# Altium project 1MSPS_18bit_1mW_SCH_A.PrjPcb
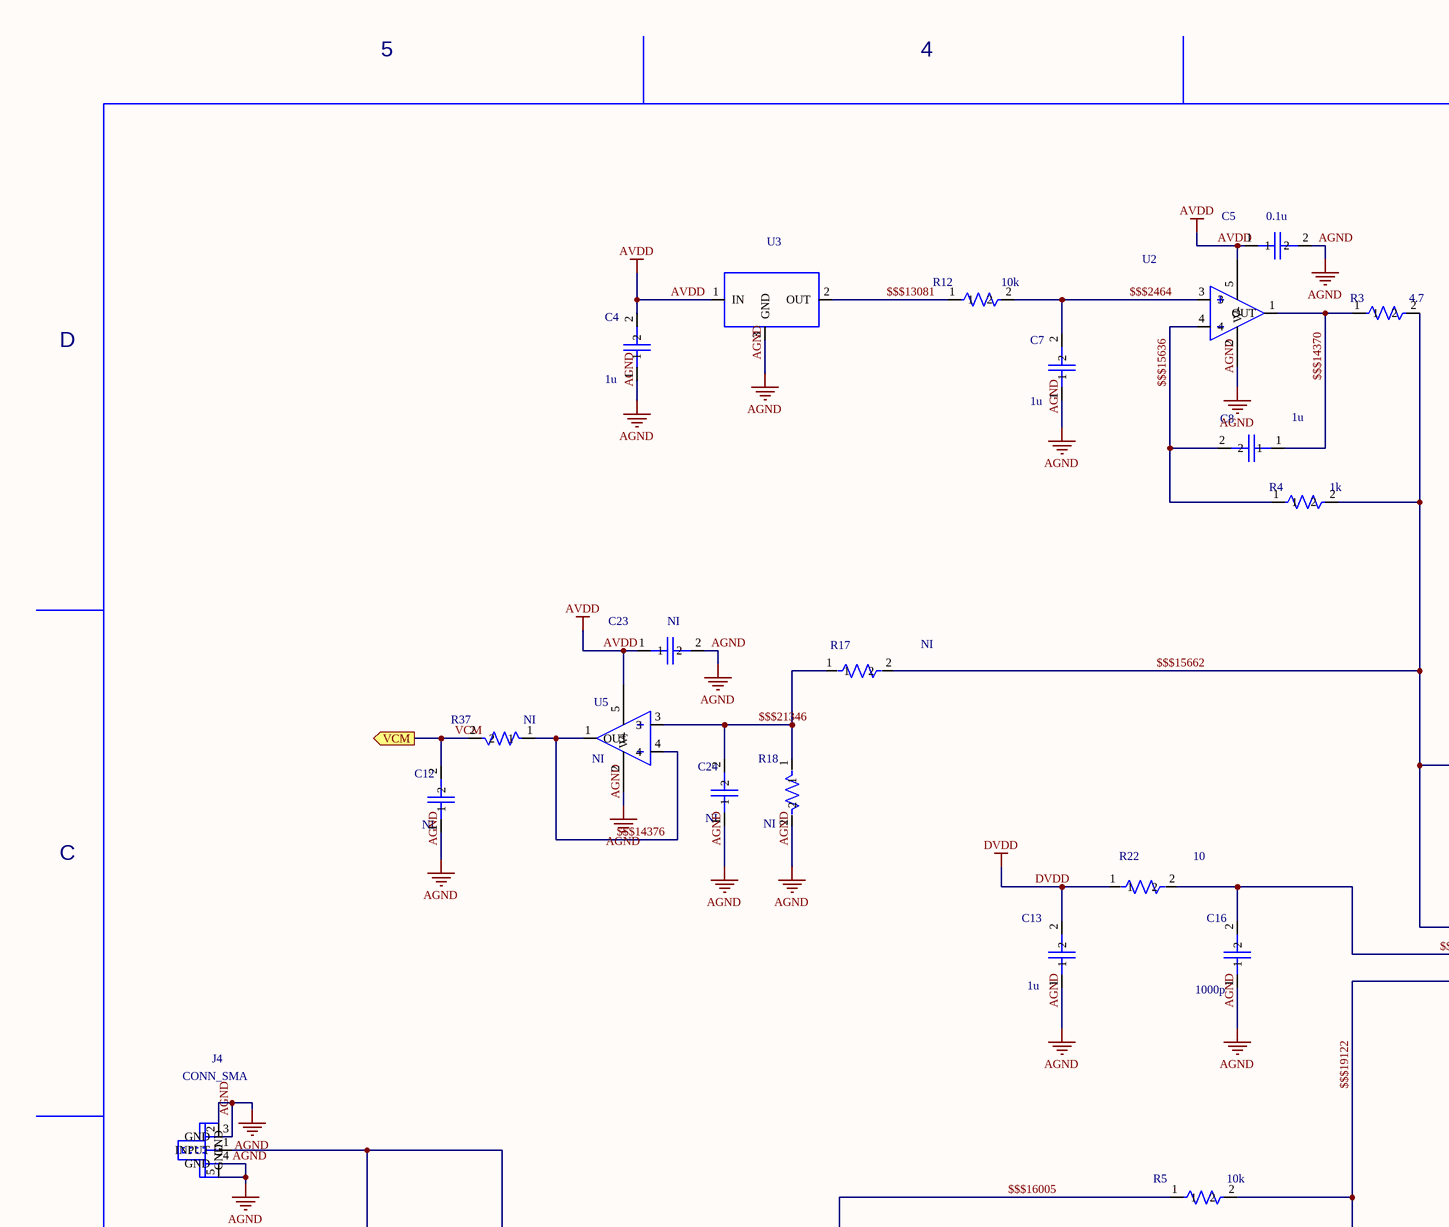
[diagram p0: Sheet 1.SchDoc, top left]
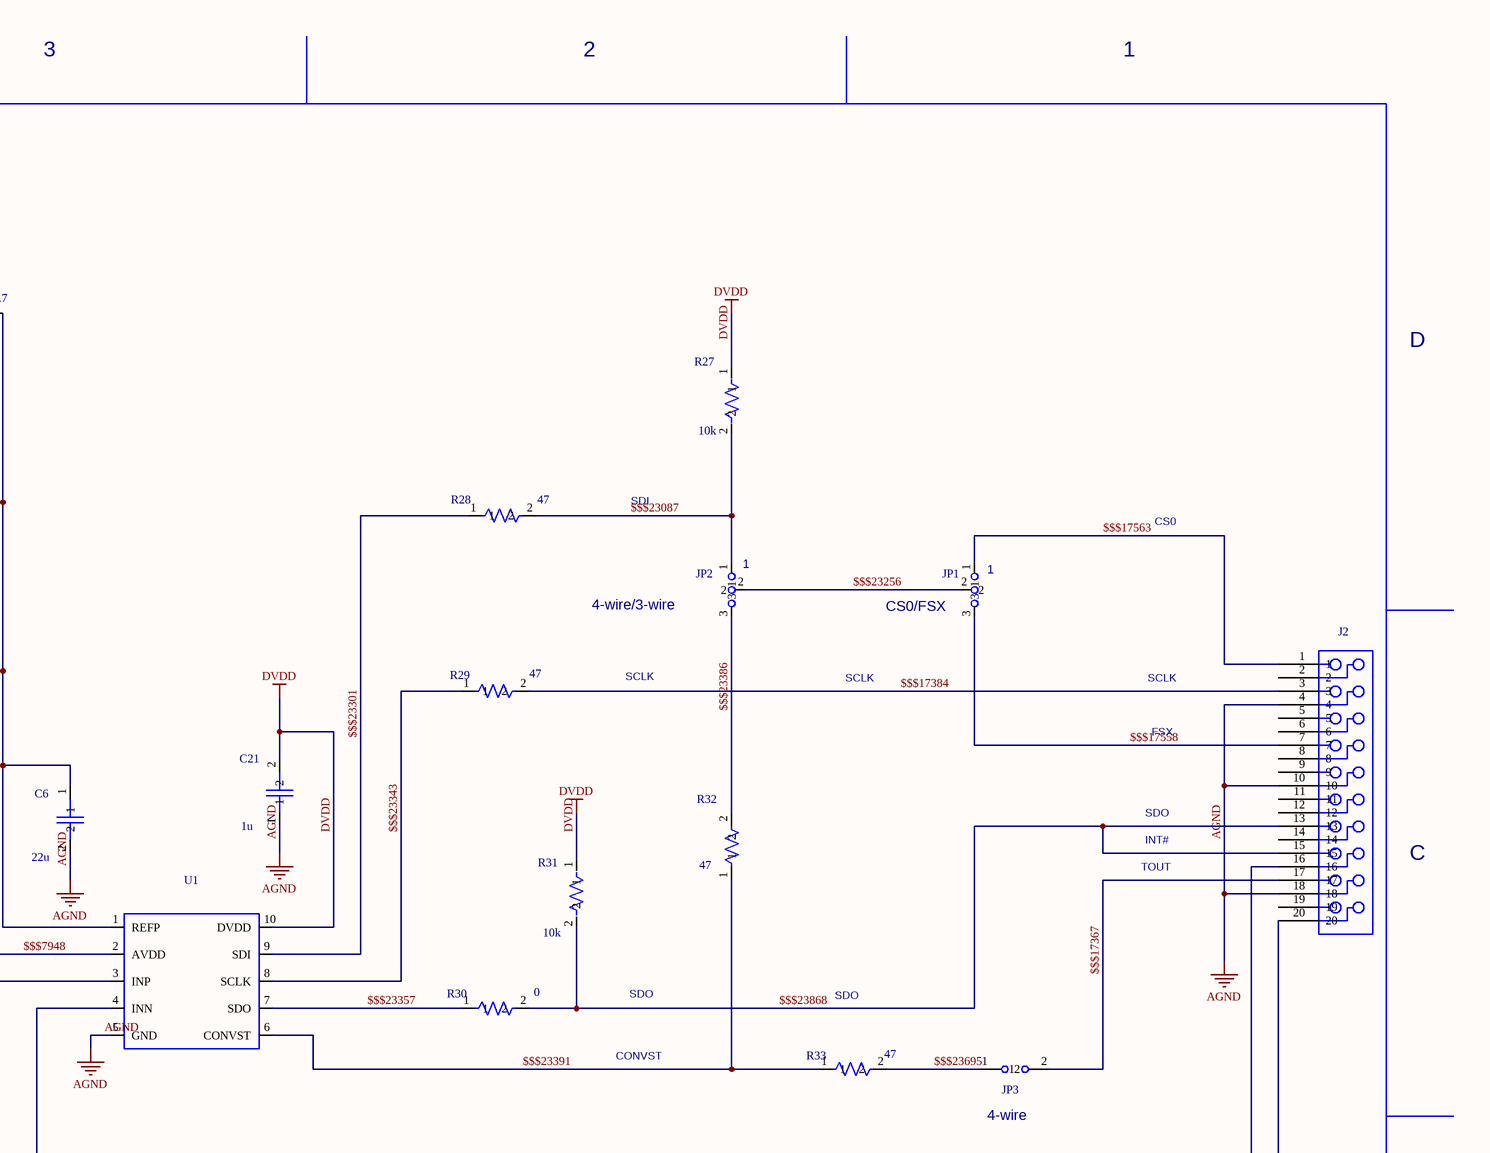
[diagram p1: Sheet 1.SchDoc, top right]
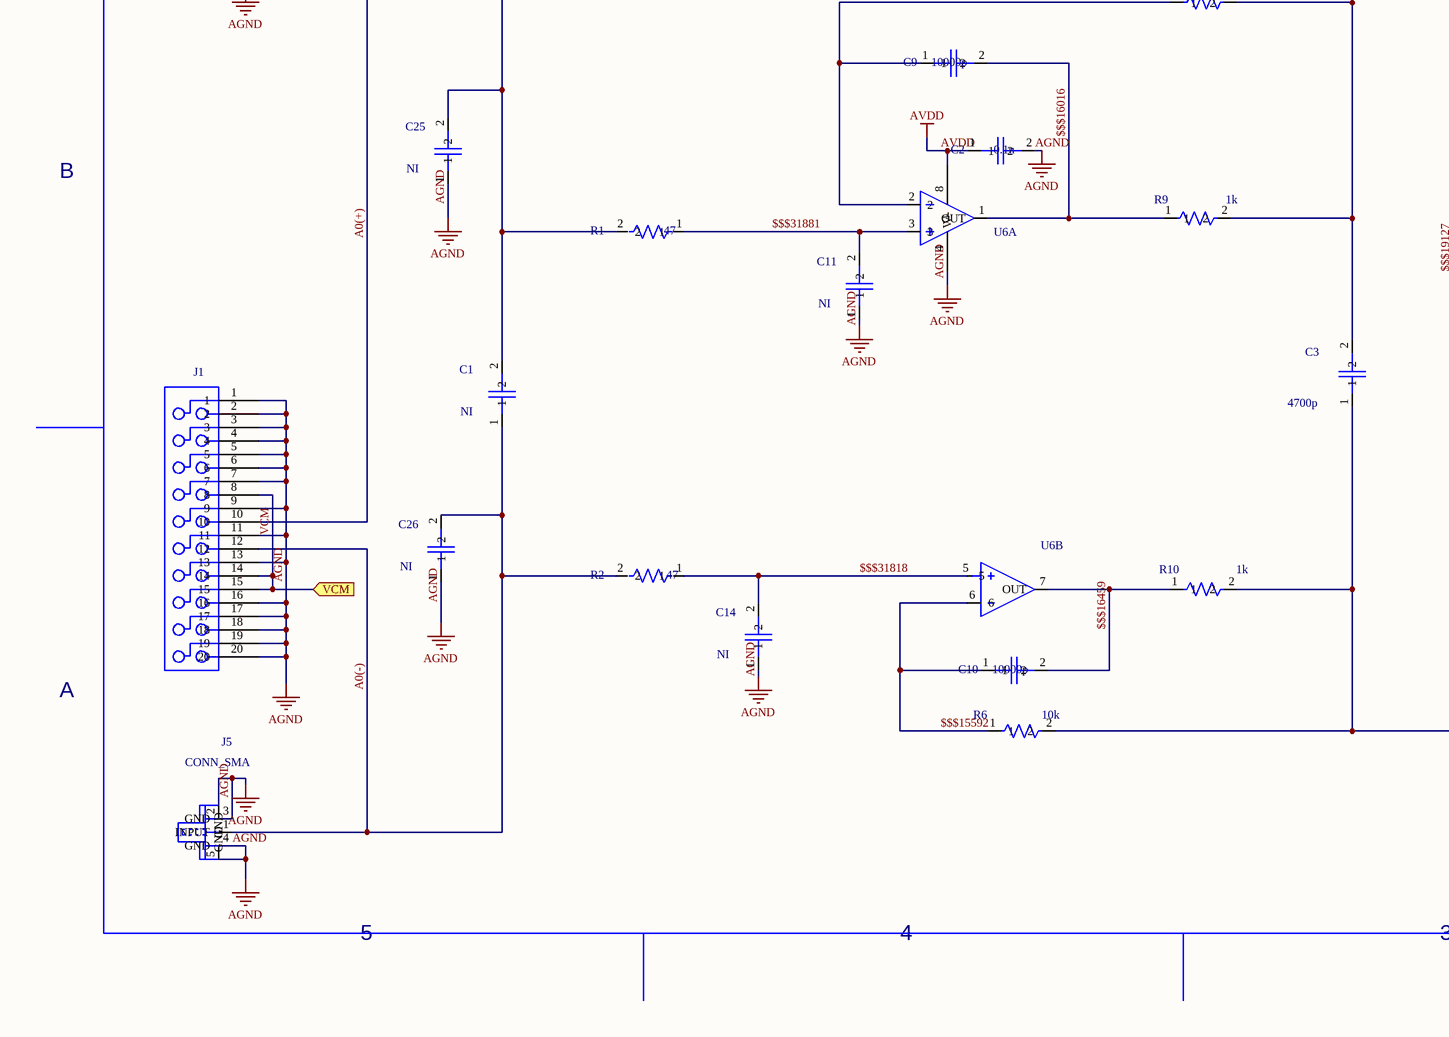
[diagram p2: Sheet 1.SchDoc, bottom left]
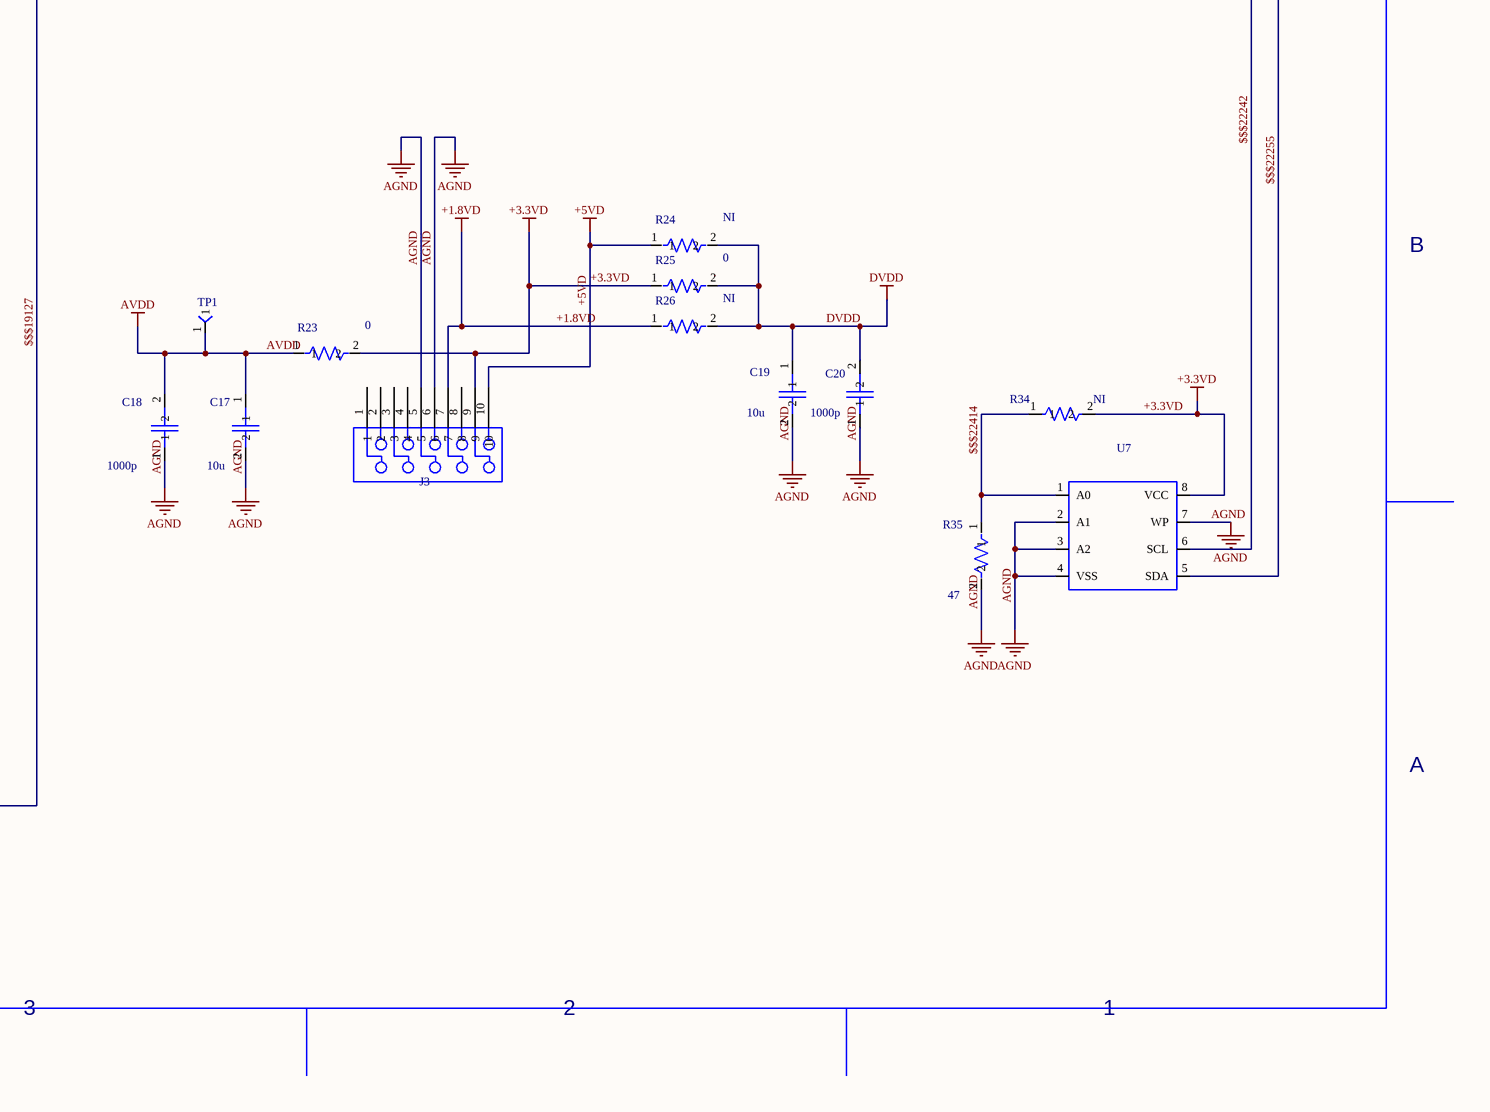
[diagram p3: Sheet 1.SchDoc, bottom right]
1 sheet, 65 parts. Net scope: flat (ports and power ports of the same name join across sheets).

## Sheet Sheet 1.SchDoc: TI Design 18bit 1MSPS 35mW
size 558 x 431 mm; DrawnBy: Rafael Ordonez; Revision: A; Designer: Rafael Ordonez; Edge No.: 6548606

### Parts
C1  value NI  (hidden comment: C0603)
C2  value 0.1u  (hidden comment: C0603)
C3  value 4700p  (hidden comment: C0603)
C4  value 1u  (hidden comment: C0603)
C5  value 0.1u  (hidden comment: C0603)
C6  value 22u  (hidden comment: C1206)
C7  value 1u  (hidden comment: C0603)
C8  value 1u  (hidden comment: C0603)
C9  value 10000p  (hidden comment: C0603)
C10  value 10000p  (hidden comment: C0603)
C11  value NI  (hidden comment: C0603)
C12  value NI  (hidden comment: C0603)
C13  value 1u  (hidden comment: C0603)
C14  value NI  (hidden comment: C0603)
C16  value 1000p  (hidden comment: C0603)
C17  value 10u  (hidden comment: C1206)
C18  value 1000p  (hidden comment: C0603)
C19  value 10u  (hidden comment: C1206)
C20  value 1000p  (hidden comment: C0603)
C21  value 1u  (hidden comment: C0603)
C23  value NI  (hidden comment: C0603)
C24  value NI  (hidden comment: C0603)
C25  value NI  (hidden comment: C0603)
C26  value NI  (hidden comment: C0603)
J1  HEADER_TSM-110-01-T-DV-P_TH  (value not drawn)
J2  HEADER_TSM-110-01-T-DV-P_TH  (value not drawn)
J3  HEADER_TSM-105-01-T-DV-P_TH  (value not drawn)
J4  CONN_SMA
J5  CONN_SMA
JP1  JUMPER_3X100MIL  (value not drawn)
JP2  JUMPER_3X100MIL  (value not drawn)
JP3  JUMPER_2X100MIL  (value not drawn)
R1  value 47  (hidden comment: R0603)
R2  value 47  (hidden comment: R0603)
R3  value 4.7  (hidden comment: R0603)
R4  value 1k  (hidden comment: R0603)
R5  value 10k  (hidden comment: R0603)
R6  value 10k  (hidden comment: R0603)
R9  value 1k  (hidden comment: R0603)
R10  value 1k  (hidden comment: R0603)
R12  value 10k  (hidden comment: R0603)
R17  value NI  (hidden comment: R0603)
R18  value NI  (hidden comment: R0603)
R22  value 10  (hidden comment: R0603)
R23  value 0  (hidden comment: R0603)
R24  value NI  (hidden comment: R0603)
R25  value 0  (hidden comment: R0603)
R26  value NI  (hidden comment: R0603)
R27  value 10k  (hidden comment: R0603)
R28  value 47  (hidden comment: R0603)
R29  value 47  (hidden comment: R0603)
R30  value 0  (hidden comment: R0603)
R31  value 10k  (hidden comment: R0603)
R32  value 47  (hidden comment: R0603)
R33  value 47  (hidden comment: R0603)
R34  value NI  (hidden comment: R0603)
R35  value 47  (hidden comment: R0603)
R37  value NI  (hidden comment: R0603)
TP1  TP-5000-RED  (value not drawn)
U1  ADS886XIDGS  (value not drawn)
U2  OPA313  (value not drawn)
U3  REF33XXAIDBZ  (value not drawn)
U5  value NI  (hidden comment: OPA333)
U6  OPA2320  (value not drawn)  (parts A,B of 2)
U7  24XX256_SERIES  (value not drawn)

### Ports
VCM

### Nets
+1.8VD: J3.7 R26.1
+3.3VD: J3.9 J3.10 R23.2 R24.1 R25.1 R34.2 U7.8(VCC)  [also labelled +5VD]
AGND: C2.2 C4.1 C5.2 C6.2 C7.1 C11.1 C12.1 C12.2 C13.1 C14.1 C16.1 C17.2 C18.1 C19.2 C20.1 C21.1 C23.2 C24.1 C25.1 C26.1 J1.1 J1.2 J1.3 J1.4 J1.5 J1.6 J1.7 J1.8 J1.9 J1.11 J1.13 J1.14 J1.15 J1.16 J1.17 J1.18 J1.19 J1.20 J2.4 J2.10 J2.18 J3.5 J3.6 J4.2(GND) J4.3(GND) J4.4(GND) J4.5(GND) J5.2(GND) J5.3(GND) J5.4(GND) J5.5(GND) R18.2 R35.2 R37.2 U1.5(GND) U2.2(V-) U3.3(GND) U5.2(V-) U6.4(V-) U7.2(A1) U7.3(A2) U7.4(VSS) U7.7(WP) ; port VCM  [also labelled VCM]
AVDD: C2.1 C4.2 C5.1 C17.1 C18.2 C23.1 R23.1 TP1.1 U2.5(V+) U3.1(IN) U5.5(V+) U6.8(V+)
DVDD: C13.2 C19.1 C20.2 C21.2 R22.1 R24.2 R25.2 R26.2 R27.1 R31.1 U1.10(DVDD)
$$$2464: C7.2 R12.2 U2.3
$$$7948: C16.2 R22.2 U1.2(AVDD)
$$$13081: R12.1 U3.2(OUT)
$$$14370: C8.1 R3.1 U2.1(OUT)
$$$14376: R37.1 U5.1(OUT) U5.4
$$$15592: C10.1 R6.1 U6.6
$$$15636: C8.2 R4.1 U2.4
$$$15662: C6.1 R3.2 R4.2 R17.2 U1.1(REFP)
$$$16005: C9.1 R5.1 U6.2
$$$16016: C9.2 R9.1 U6.1(OUT)
$$$16459: C10.2 R10.1 U6.7(OUT)
$$$17367: J2.17 JP3.2
$$$17384: J2.3 R29.2
$$$17558: J2.7 JP1.3
$$$17563: J2.1 JP1.1
$$$19122: C3.2 R5.2 R9.2 U1.3(INP)
$$$19127: C3.1 R6.2 R10.2 U1.4(INN)
$$$21346: C24.2 R17.1 R18.1 U5.3
$$$22242: J2.16 U7.6(SCL)
$$$22255: J2.20 U7.5(SDA)
$$$22414: R34.1 R35.1 U7.1(A0)
$$$23087: JP2.1 R27.2 R28.2
$$$23256: JP1.2 JP2.2
$$$23301: R28.1 U1.9(SDI)
$$$23343: R29.1 U1.8(SCLK)
$$$23357: R30.1 U1.7(SDO)
$$$23386: JP2.3 R32.2
$$$23391: R32.1 R33.1 U1.6(CONVST)
$$$23695: JP3.1 R33.2
$$$23868: J2.13 J2.15 R30.2 R31.2
$$$31818: C14.2 R2.1 U6.5
$$$31881: C11.2 R1.1 U6.3
A0(+): C1.2 C25.2 J1.10 J4.1(INPUT) R1.2
A0(-): C1.1 C26.2 J1.12 J5.1(INPUT) R2.2

Not connected (* = marked no-connect by the designer): J2 2 5 6 8 9 11 12 14 19; J3 1 2 3 4 8

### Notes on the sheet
- 5
- 4
- 3
- 2
- 1
- D
- SDI
- CS0
- (near JP2) 1
- (near JP1) 1
- (near JP2) 4-wire/3-wire
- (near JP1) CS0/FSX
- SCLK
- FSX
- C
- TOUT
- SDO
- INT#
- CONVST
- (near JP3) 4-wire
- B
- A

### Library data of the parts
C1 C11 C12 C14 C23-C26 = C0603: Not Installed 0603; Area: 5650; PCB DECAL: C603
C2 C5 = C0603: Capacitor, X7R Ceramic +/-10%, 25WV, 0603; MFR: Murata; Part Number: GRM188R71E104KA01D; Area: 5650; PCB DECAL: C603
C3 = C0603: Capacitor, NP0 Ceramic +/-5%, 50WV, 0603; MFR: TDK; Part Number: C1608C0G1H472J080AA; Area: 5650; PCB DECAL: C603
C4 C7 C8 C13 C21 = C0603: Capacitor, X7R Ceramic +/-10%, 25WV, 0603; MFR: Murata; Part Number: GRM188R71E105KA12D; Area: 5650; PCB DECAL: C603
C6 = C1206: Capacitor, X5R Ceramic +/-20%, 16WV, 1206; MFR: TDK; Part Number: C3216X5R1C226M160AB; Area: 15390
C9 C10 = C0603: Capacitor, NP0 Ceramic +/-5%, 50WV, 0603; MFR: TDK; Part Number: C1608C0G1H103J080AA; Area: 5650; PCB DECAL: C603
C16 C18 C20 = C0603: Capacitor, C0G Ceramic +/-5%, 50WV, 0603; MFR: Murata; Part Number: GRM1885C1H102JA01D; Area: 5650; PCB DECAL: C603
C17 C19 = C1206: Capacitor, X7R Ceramic +/-10%, 16WV, 1206; MFR: TDK; Part Number: C3216X7R1C106K; Area: 15390
J1 J2 = HEADER_TSM-110-01-T-DV-P_TH: Header 20 Pin SMT Plug(Top)/Socket(Bottom), .100" Gold (2x10); Part Number: TSM-110-01-L-DV-P (Top) and SSW-110-22-F-D-VS-K (Bottom); MFR: Samtec; Area: 391400; PCB DECAL: HEADER_TSM-110-XX-DV_TH
J3 = HEADER_TSM-105-01-T-DV-P_TH: Header 10 Pin SMT Plug(Top)/Socket(Bottom),  .100" Gold (2x5); Part Number: TSM-105-01-L-DV-P (Top) and SSW-105-22-F-D-VS-K (Bottom); MFR: Samtec; Area: 391400; PCB DECAL: HEADER_TSM-105-XX-DV_TH
J4 J5 = CONN_SMA: CONN SMA JACK STRAIGHT PCB; MFR: Amphenol; Part Number: 132134; PCB DECAL: CONNECTOR_SMA
JP1 JP2 = JUMPER_3X100MIL: Header Strip, 3 pin .100" Gold (1x3); MFR: Samtec; Part Number: TSW-103-07-L-S; Reference: \\vette02\pmp_pcb\pcad_pdf's\pec36saan.pdf; Second Source: C:\program files\p-cad 2004\pcad_pdf's\pec36saan.pdf; area: 30000; PCB DECAL: HDR100_1X3
JP3 = JUMPER_2X100MIL: Header Strip, 2 pin .100" Gold (1x2); MFR: Samtec; Part Number: TSW-102-07-L-S; Reference: \\vette02\pmp_pcb\pcad_pdf's\pec36saan.pdf; Second Source: C:\program files\p-cad 2004\pcad_pdf's\pec36saan.pdf; area: 20000; PCB DECAL: HDR100_1X2
R1 R2 R28 R29 R32 R33 R35 = R0603: Resistor, Thick Film Chip, 1%, 1/10W, 0603; MFR: Panasonic; Part Number: ERJ-3EKF47R0V; Area: 2800
R3 = R0603: Resistor, Thick Film Chip, 1%, 1/10W, 0603; MFR: Vishay/Dale; Part Number: CRCW06034R70FKEA; Area: 2800
R4 R9 R10 = R0603: Resistor, Thick Film Chip, 1%, 1/10W, 0603; MFR: Panasonic; Part Number: ERJ-3EKF1001V; Area: 2800
R5 R6 R12 R27 R31 = R0603: Resistor, Thick Film Chip, 1%, 1/10W, 0603; MFR: Panasonic; Part Number: ERJ-3EKF1002V; Area: 2800
R17 R18 R24 R26 R34 R37 = R0603: Not Installed 0603; Area: 2800
R22 = R0603: Resistor, Thick Film Chip, 1%, 1/10W, 0603; MFR: Vishay/Dale; Part Number: CRCW060310R0FKEA; Area: 2800
R23 R25 R30 = R0603: Resistor, Thick Film Chip, 1/10W, 0603; MFR: Panasonic; Part Number: ERJ-3GEY0R00V; Area: 2800
TP1 = TP-5000-RED: Test Point,  Red, Thru Hole Color Keyed; MFR: Keystone; Reference: \\vette02\pmp_pcb\pcad_pdf's\Keystone-SMT-TH_Test point.pdf; Second Source: C:\program files\p-cad 2004\pcad_pdf's\Keystone-SMT-TH_Test point.pdf; area: 10.000; Value: 5000; PCB DECAL: TH-40
U1 = ADS886XIDGS: IC ADC 1MSPS 18bit Fully-Diff MSOP-10; MFR: TI; Part Number: ADS8881IDGS; Second Source: C:\program files\p-cad 2004\pcad_pdf's\ADS88xx.pdf; Reference: \\vette02\pmp_pcb\pcad_pdf's\ADS88xx.pdf; Area: 44100; PCB DECAL: DGS_10P
U2 = OPA313: IC OPAMP R-R 1MHZ SOT23-5; Part Number: OPA313IDBV; MFR: TI; Area: 28620; PCB DECAL: DBV-5
U3 = REF33XXAIDBZ: IC, 30 ppm/°C, 3.9 µA  2.5-Voltage Reference; Part Number: REF3325AIDBZ; Mfr: TI; Area: 30600; Second Source: C:\program files\p-cad 2004\pcad_pdf's\ref3318.pdf; Reference: \\vette02\pmp_pcb\pcad_pdf's\ref3318.pdf; PCB DECAL: SOT-23
U5 = OPA333: IC OPAMP SOT23-5 (Not installed); Area: 28620; PCB DECAL: DBV-5
U6 = OPA2320: IC OPAMP R-R 350KHz DUAL 8MSOP; Part Number: OPA2333AIDGK; Mfr: TI; Area: 35250; PCB DECAL: DGK8
U7 = 24XX256_SERIES: IC EEPROM 256KBIT 400KHZ 8TSSOP; Part Number: 24LC256-I/ST; MFR: Microchip; Second Source: C:\program files\p-cad 2004\pcad_pdf's\E2.pdf; Reference: \\vette02\pmp_pcb\pcad_pdf's\E2.pdf; Area: 30.38 mm; PCB DECAL: TSSOP8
